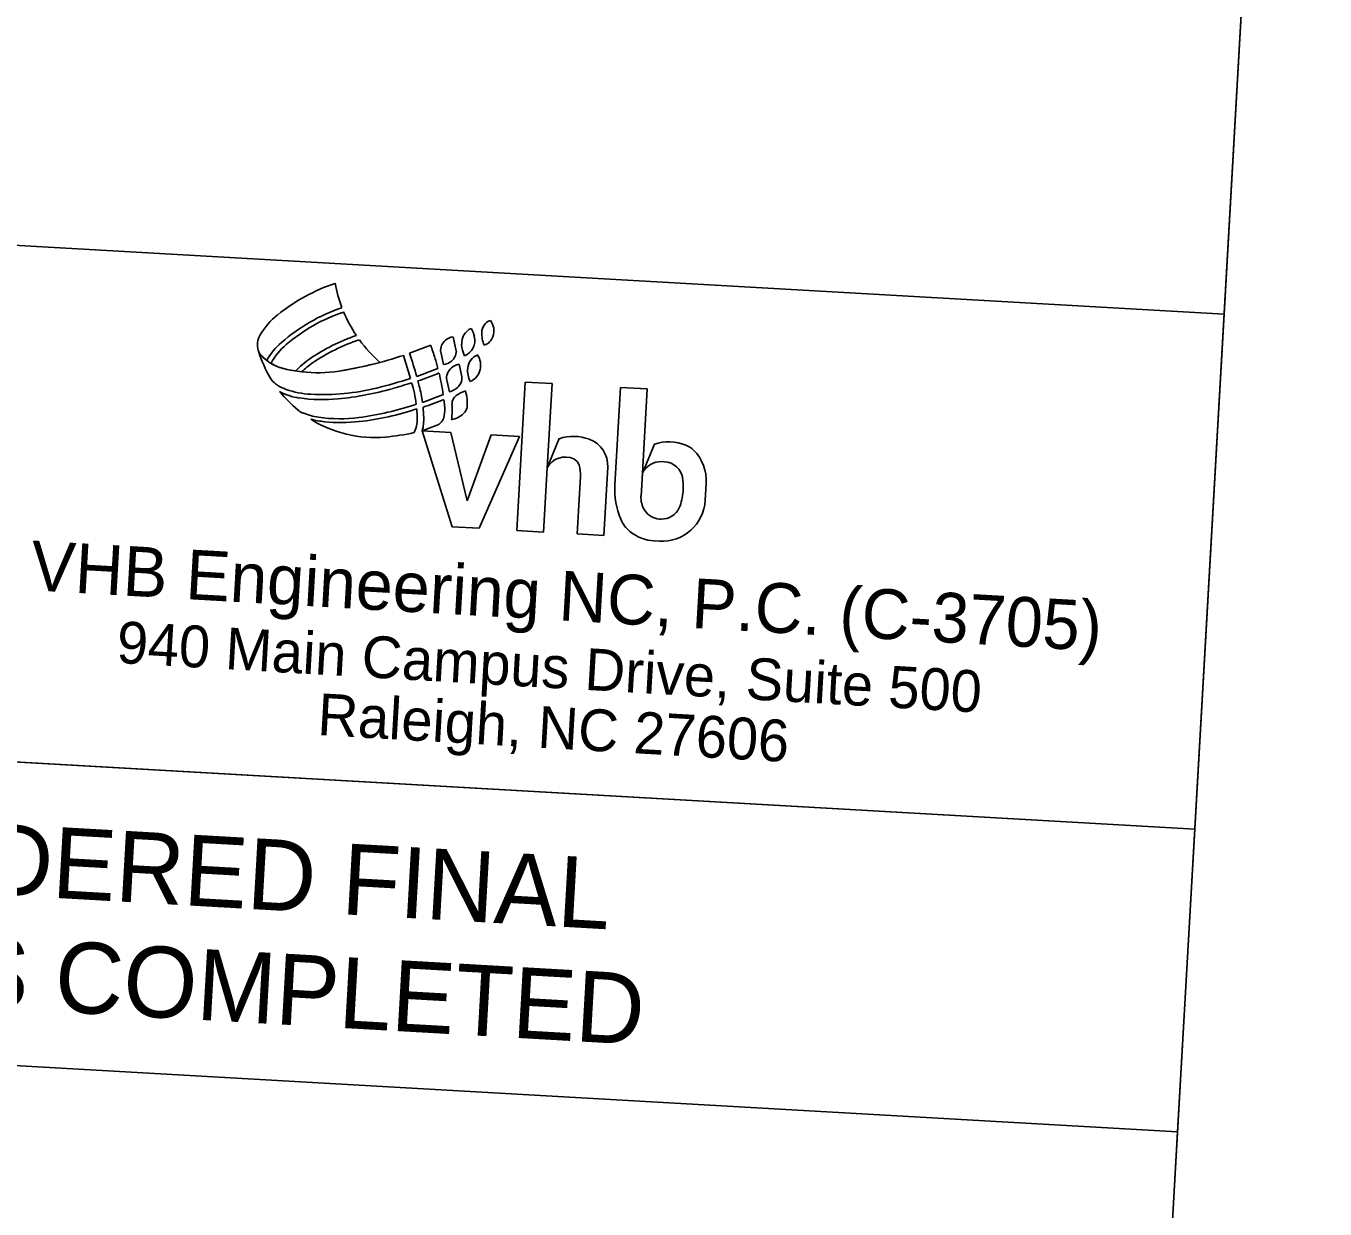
# Model space of a CAD drawing. Extents: x 2604316 to 2606605, y 617090 to 619543.
# Drawn here: x 2605948.3 to 2606049.1, y 618780.5 to 618872.2 of the extents above; entities that cross this region are included whole.
import ezdxf

# ---------------------------------------------------------------- set-up
doc = ezdxf.new("R2010")
doc.units = 0
for name, color, linetype in [('Default', 7, 'Continuous'), ('Scratch_Level_1', 7, 'Continuous'), ('Sheet Plan And Profile CELL', 7, 'Continuous')]:
    doc.layers.add(name, color=color, linetype=linetype)

msp = doc.modelspace()

# ---------------------------------------------------------------- linework, layer by layer
at = {"layer": 'Default'}
for p, q in [((2605981.71, 618846.98), (2605981.47, 618848.1)), ((2605978.16, 618844.87), (2605977.63, 618846.66)), ((2605980.51, 618846.94), (2605980.73, 618845.94)), ((2605982.15, 618844.99), (2605981.93, 618845.97)), ((2605980.99, 618844.73), (2605981.19, 618843.82)), ((2605987.06, 618844.59), (2605986.41, 618833.08)), ((2605989.14, 618844.47), (2605987.06, 618844.59)), ((2605994.44, 618844.17), (2605994.02, 618836.62)), ((2605996.52, 618844.05), (2605994.44, 618844.17)), ((2605979.08, 618840.8), (2605980.16, 618841.21)), ((2605981.3, 618840.68), (2605979.08, 618840.8)), ((2605979.08, 618840.8), (2605981.4, 618833.37)), ((2605982.56, 618835.39), (2605981.3, 618840.68)), ((2605984.42, 618840.5), (2605982.56, 618835.39)), ((2605983.49, 618833.25), (2605986.63, 618840.37)), ((2605986.63, 618840.37), (2605984.42, 618840.5)), ((2605989.7, 618840.2), (2605988.76, 618837.94)), ((2605997.09, 618839.78), (2605996.15, 618837.52)), ((2605997.67, 618838.42), (2605997.86, 618838.41)), ((2605993.16, 618832.7), (2605993.46, 618837.98)), ((2605991.34, 618837.27), (2605991.08, 618832.82)), ((2605999.31, 618836.32), (2605999.3, 618836.1)), ((2606001.02, 618835.42), (2606001.09, 618836.73)), ((2605981.4, 618833.37), (2605983.49, 618833.25)), ((2605997.6, 618833.96), (2605997.47, 618833.97)), ((2605986.41, 618833.08), (2605988.48, 618832.96)), ((2605991.08, 618832.82), (2605993.16, 618832.7)), ((2605997.07, 618832.27), (2605997.47, 618832.25)), ((2605839.28, 618821.29), (2606038.99, 618809.92)), ((2605839.28, 618821.29), (2606038.99, 618809.92)), ((2606038.99, 618809.91), (2606037.65, 618786.45)), ((2606038.99, 618809.91), (2606037.65, 618786.45)), ((2606037.66, 618786.46), (2605837.94, 618797.83)), ((2606037.66, 618786.46), (2605837.94, 618797.83))]:
    msp.add_line(p, q, dxfattribs=at)
msp.add_lwpolyline([(2605941.43, 618855.54), (2606041.27, 618849.85), (2606038.99, 618809.92), (2605939.15, 618815.61)], close=True, dxfattribs=at)
for points in [[(2605988.48, 618832.96), (2605988.76, 618837.94), (2605989.14, 618844.47)], [(2605996.05, 618835.75), (2605996.15, 618837.52), (2605996.52, 618844.05)]]:
    msp.add_lwpolyline(points, dxfattribs=at)
for centre, major_axis, start_param, end_param in [((2605976.88, 618838.62), (14.34, -0.82), 1.950459, 2.306295), ((2605982.74, 618854.1), (10.56, -0.6), 3.374816, 3.559712), ((2605971.51, 618845.27), (5.81, -0.33), 2.306295, 2.663056), ((2605977.35, 618837.12), (13.96, -0.79), 1.955908, 2.345415), ((2605977.35, 618837.12), (13.6, -0.77), 1.954608, 2.331375), ((2605982.74, 618854.1), (10.56, -0.6), 3.593328, 3.791245), ((2605983.42, 618847.59), (1.28, -0.07), 2.069357, 3.26373), ((2605980.7, 618847.52), (2.49, -0.14), 0.300085, 0.573578), ((2605984.67, 618848.43), (0.981, -0.056), 1.950799, 3.19085), ((2605986.18, 618848.42), (2.49, -0.14), 3.190836, 3.597778), ((2605983.27, 618848.55), (1.36, -0.08), 6.010502, 6.978239), ((2605967.81, 618847.47), (1.51, -0.09), 2.663056, 3.487291), ((2605971.63, 618843.67), (5.28, -0.3), 2.345415, 2.685879), ((2605971.71, 618843.77), (4.9, -0.28), 2.331375, 2.717794), ((2605978.85, 618833.89), (15.09, -0.86), 1.956929, 2.223843), ((2605978.85, 618833.89), (14.71, -0.84), 1.949325, 2.223843), ((2605982.74, 618854.1), (10.56, -0.6), 3.829221, 4.05458), ((2605967.99, 618875.31), (30.18, -1.72), 5.110242, 5.168312), ((2605942.26, 618834.83), (39.48, -2.25), 0.355324, 0.381952), ((2605981.52, 618847.04), (1.02, -0.06), 2.340862, 3.293303), ((2605981.69, 618846.84), (1.28, -0.07), 1.805558, 2.340862), ((2605984.62, 618847.67), (2.49, -0.14), 3.26373, 3.631752), ((2605981.87, 618847.81), (1.28, -0.07), 5.158115, 6.583255), ((2605983.55, 618848.45), (1.06, -0.06), 5.088672, 6.010509), ((2605975.42, 618849.73), (9.43, -0.54), 3.487291, 3.49224), ((2605967.1, 618847.21), (0.755, -0.043), 3.492238, 3.942132), ((2605967.1, 618847.21), (0.755, -0.043), 3.492238, 3.942132), ((2605975.42, 618849.73), (9.43, -0.54), 3.492238, 3.737263), ((2605969.27, 618849.21), (3.7, -0.21), 3.942115, 4.117328), ((2605969.27, 618849.21), (3.7, -0.21), 3.942115, 4.535322), ((2605974.18, 618840.76), (6.79, -0.39), 2.223843, 2.440018), ((2605967.99, 618875.31), (30.18, -1.72), 4.923489, 5.093727), ((2605942.26, 618834.83), (37.73, -2.15), 0.330018, 0.379866), ((2605961.43, 618840.72), (19.46, -1.11), 0.312292, 0.355324), ((2605980.7, 618847.01), (1.02, -0.06), 5.445151, 6.311085), ((2605983.81, 618845.56), (1.21, -0.07), 1.982585, 3.114577), ((2605982.02, 618845.88), (1.58, -0.09), 6.124862, 6.873863), ((2605969.27, 618849.21), (3.7, -0.21), 4.225969, 4.535322), ((2605970.95, 618856.27), (10.94, -0.62), 4.535322, 4.613027), ((2605970.95, 618856.27), (10.94, -0.62), 4.535322, 4.657076), ((2605974.18, 618840.76), (6.41, -0.36), 2.223843, 2.396036), ((2605970.95, 618856.27), (10.94, -0.62), 4.657076, 4.923489), ((2605970.95, 618856.27), (10.94, -0.62), 4.657076, 4.923489), ((2605967.99, 618875.31), (30.18, -1.72), 4.923489, 5.030725), ((2605967.99, 618875.31), (32.06, -1.83), 5.107726, 5.162272), ((2605980.53, 618847.21), (1.28, -0.07), 4.922279, 5.445148), ((2605981.95, 618844.92), (0.981, -0.056), 2.294387, 3.400315), ((2605982.23, 618844.57), (1.43, -0.08), 1.838184, 2.294391), ((2605984.71, 618845.48), (2.11, -0.12), 3.114567, 3.617561), ((2605982.32, 618845.82), (1.28, -0.07), 5.137017, 6.124854), ((2605968.61, 618845.66), (1.51, -0.09), 3.737263, 4.155114), ((2605969.56, 618847.02), (3.17, -0.18), 4.155114, 4.433304), ((2605967.99, 618875.31), (32.04, -1.83), 5.007435, 5.091777), ((2605967.99, 618875.31), (32.39, -1.84), 5.043468, 5.091439), ((2605968.12, 618841.51), (10.56, -0.6), 0.186675, 0.34709), ((2605967.99, 618875.31), (32.42, -1.85), 5.106941, 5.160619), ((2605942.26, 618834.83), (37.73, -2.15), 0.309699, 0.320394), ((2605961.43, 618840.72), (19.46, -1.11), 0.205325, 0.293478), ((2605981.17, 618844.92), (0.981, -0.056), 5.669754, 6.410867), ((2605970.21, 618847.99), (4.68, -0.27), 4.281835, 4.626581), ((2605975.42, 618849.73), (9.43, -0.54), 3.869789, 4.084312), ((2605970.81, 618850.58), (6.94, -0.4), 4.433304, 4.717272), ((2605971.34, 618855.85), (12.6, -0.72), 4.626581, 4.866042), ((2605971.37, 618861.38), (17.73, -1.01), 4.717272, 5.007435), ((2605970.23, 618867.35), (24.14, -1.38), 4.866042, 5.043468), ((2605968.12, 618841.51), (11.06, -0.63), 0.192744, 0.309699), ((2605967.99, 618875.31), (34.1, -1.94), 5.100586, 5.150688), ((2605980.81, 618845.2), (1.43, -0.08), 5.034707, 5.66976), ((2605982.22, 618842.89), (0.83, -0.047), 2.288613, 3.208516), ((2605983.01, 618841.87), (2.11, -0.12), 1.905419, 2.288613), ((2605978.86, 618842.9), (3.7, -0.21), 6.258511, 6.615609), ((2605970.4, 618843.58), (1.51, -0.09), 4.084312, 4.375641), ((2605971.29, 618864.33), (22.64, -1.29), 4.896065, 5.098239), ((2605971.88, 618862.56), (21.13, -1.2), 4.878361, 5.095384), ((2605968.12, 618841.51), (10.56, -0.6), 0.080866, 0.152313), ((2605967.99, 618875.31), (34.47, -1.96), 5.098273, 5.148033), ((2605968.12, 618841.51), (11.06, -0.63), 0.08898, 0.158557), ((2605961.43, 618840.72), (19.46, -1.11), 0.162521, 0.185756), ((2605977.8, 618842.46), (3.02, -0.17), 6.17953, 6.445706), ((2605975.13, 618842.43), (6.26, -0.36), 6.218327, 6.411973), ((2605981.74, 618842.77), (0.83, -0.047), 5.49053, 6.137671), ((2605971.7, 618846.73), (4.9, -0.28), 4.375641, 4.631331), ((2605972.2, 618848.43), (6.94, -0.4), 4.511808, 4.670453), ((2605975.42, 618849.73), (9.43, -0.54), 4.213149, 4.853258), ((2605972.66, 618853.61), (11.85, -0.67), 4.631331, 4.896065), ((2605972.78, 618854.3), (12.83, -0.73), 4.670453, 4.878361), ((2605976.43, 618841.71), (2.26, -0.13), 5.862276, 6.364042), ((2605975.42, 618841.74), (3.77, -0.21), 6.089473, 6.37216), ((2605979.82, 618842.13), (0.981, -0.056), 5.129856, 6.17953), ((2605980.89, 618843.73), (2.11, -0.12), 4.991009, 5.49053), ((2605974.85, 618856.51), (16.22, -0.92), 4.853258, 4.99278), ((2605990.81, 618836.86), (3.51, -0.2), 1.271815, 1.948427), ((2605991.27, 618838.1), (2.19, -0.12), 6.283185, 7.555001), ((2605998.19, 618836.44), (3.51, -0.2), 1.243417, 1.948427), ((2605998.83, 618838.02), (1.81, -0.1), 0.841181, 1.243417), ((2605997.74, 618836.93), (3.36, -0.19), 0, 0.841181), ((2605990.16, 618837.19), (-1.58, 0.09), 4.330931, 5.84316), ((2605990.51, 618837.94), (-0.755, 0.043), 3.478495, 4.330931), ((2605997.58, 618836.84), (1.58, -0.09), 1.570796, 2.75299), ((2605997.78, 618836.9), (1.51, -0.09), 0.218399, 1.570796), ((2605988.7, 618837.42), (2.64, -0.15), 0, 0.336903), ((2606000.05, 618836.28), (-6.04, 0.34), 0, 0.452165), ((2605995.54, 618836.54), (3.77, -0.21), 6.283185, 6.501584), ((2605997.93, 618835.65), (-1.89, 0.11), 6.283185, 6.906012), ((2605997.66, 618835.61), (3.36, -0.19), 4.712389, 6.283185), ((2605995.53, 618836.31), (3.77, -0.21), 5.93764, 6.283185), ((2605997.55, 618835.4), (-1.43, 0.08), 0.622827, 1.570796), ((2605997.68, 618835.4), (1.43, -0.08), 4.712389, 5.93764), ((2605996.7, 618834.88), (-2.41, 0.14), 0.452165, 0.946963), ((2605997.26, 618835.56), (-3.29, 0.19), 0.946963, 1.570796)]:
    msp.add_ellipse(centre, major_axis=major_axis, ratio=0.999914, start_param=start_param, end_param=end_param, dxfattribs=at)
at = {"layer": 'Scratch_Level_1'}
msp.add_lwpolyline([(2606037.66, 618786.46), (2605837.94, 618797.83), (2605849.36, 618998.56), (2604589.3, 619070.32), (2604537.44, 618159.71), (2605997.22, 618076.57)], close=True, dxfattribs=at)
msp.add_lwpolyline([(2606037.66, 618786.46), (2605837.94, 618797.83), (2605849.36, 618998.56), (2604589.3, 619070.32), (2604537.44, 618159.71), (2605997.22, 618076.57)], close=True, dxfattribs=at)
at = {"layer": 'Sheet Plan And Profile CELL'}
msp.add_line((2605839.28, 618821.29), (2606038.99, 618809.92), dxfattribs=at)
for points in [[(2606049.09, 618987.18), (2604551.51, 619072.48), (2604491.81, 618024.18), (2605989.38, 617938.88)], [(2605947.83, 618967.86), (2606047.65, 618962.19), (2606041.27, 618849.85), (2605941.43, 618855.53)]]:
    msp.add_lwpolyline(points, close=True, dxfattribs=at)

# ---------------------------------------------------------------- texts
at = {"layer": 'Default'}
for s, height, rotation, p in [('VHB Engineering NC, P.C. (C-3705)', 3.8596, 356.7403, (2605948.63, 618828.45)), ('940 Main Campus Drive, Suite 500', 3.2388, 356.7015, (2605955.32, 618822.82)), ('Raleigh, NC 27606', 3.2388, 356.7015, (2605970.9, 618817.23)), ('DOCUMENT NOT CONSIDERED FINAL', 5.5, 356.7403, (2605859.73, 618809.77)), ('DOCUMENT NOT CONSIDERED FINAL', 5.5, 356.7403, (2605859.73, 618809.77)), ('UNLESS ALL SIGNATURES COMPLETED', 5.5, 356.7403, (2605854.16, 618801.27)), ('UNLESS ALL SIGNATURES COMPLETED', 5.5, 356.7403, (2605854.16, 618801.27))]:
    msp.add_text(s, height=height, rotation=rotation, dxfattribs=at).set_placement(p)

doc.saveas('drawing.dxf')
